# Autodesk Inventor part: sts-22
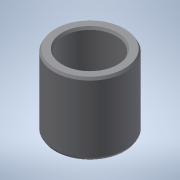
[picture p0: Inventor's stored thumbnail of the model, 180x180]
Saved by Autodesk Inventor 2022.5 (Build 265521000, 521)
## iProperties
Created: 2016-12
Part Number: sts-22
Material: 一般
Document SubType Name: Modeling
Designer: imaocorp
Density: 1 g/cm^3
Appearance: 既定
Author: imaocorp
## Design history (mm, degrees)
node "sts-22.x_t1"
node "sts-22"
node "Base1"
